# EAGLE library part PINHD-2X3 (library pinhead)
PIN HEADER
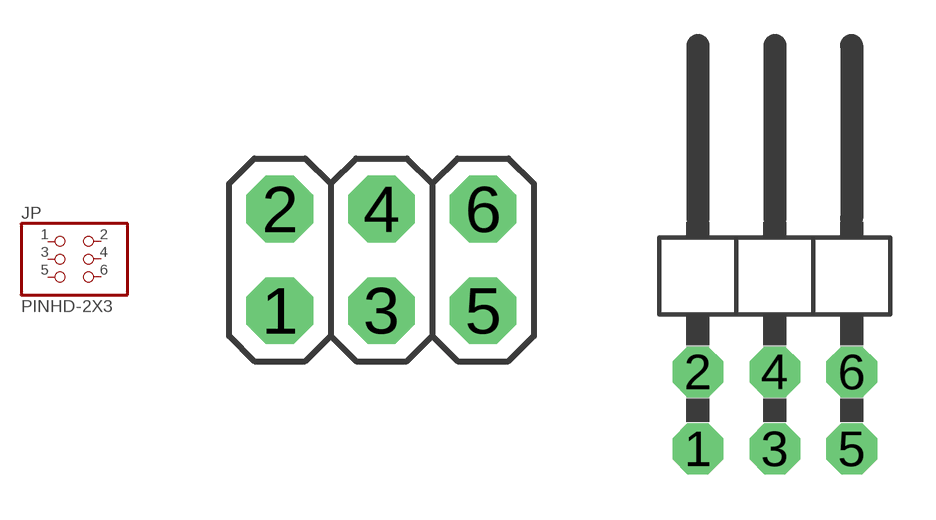
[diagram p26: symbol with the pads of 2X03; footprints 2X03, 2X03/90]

Designator prefix JP

## PINHD-2X3  [2X03]
1  1  pas
2  2  pas
3  3  pas
4  4  pas
5  5  pas
6  6  pas

## PINHD-2X3/90  [2X03/90]
Pads as for 2X03

## Footprint 2X03 (pad centres in mm)
PIN HEADER
drill 1.016 pad 1.67 octagon: 1 -2.54,-1.27; 2 -2.54,1.27; 3 0,-1.27; 4 0,1.27; 5 2.54,-1.27; 6 2.54,1.27

## Footprint 2X03/90 (pad centres in mm)
PIN HEADER
drill 1.016 pad 1.67 octagon: 1 -2.54,-6.35; 2 -2.54,-3.81; 3 0,-6.35; 4 0,-3.81; 5 2.54,-6.35; 6 2.54,-3.81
